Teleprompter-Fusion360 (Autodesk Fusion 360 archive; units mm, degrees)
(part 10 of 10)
sketch "Skizze119" plane through (0, 0, 4) normal (0, 0, 1) x axis (-1, 0, 0)
  line L1 (2.9968, -220.3404) -> (2.9969, -220.3404)
  line L2 (-0.0031, -167.3404) -> (-0.0031, -217.3404)
  line L3 (2.9969, -164.3404) -> (2.9968, -164.3404)
  line L4 (2.9969, -150.3404) -> (2.9969, -164.3404)
  line L5 (-362.0031, -150.3404) -> (2.9969, -150.3404)
  line L6 (-362.0031, -164.3404) -> (-362.0031, -150.3404)
  line L7 (-361.0031, -164.3404) -> (-362.0031, -164.3404)
  line L8 (-358.0031, -217.3404) -> (-358.0031, -167.3404)
  line L9 (-362.0031, -220.3404) -> (-361.0031, -220.3404)
  line L10 (-362.0031, -226.3404) -> (-362.0031, -220.3404)
  line L11 (-327.2391, -226.3404) -> (-362.0031, -226.3404)
  line L12 (-301.0031, -227.3404) -> (-325.0031, -227.3404)
  line L13 (-60.2391, -226.3404) -> (-298.767, -226.3404)
  line L14 (-34.0031, -227.3404) -> (-58.0031, -227.3404)
  line L15 (2.9969, -226.3404) -> (-31.767, -226.3404)
  line L16 (2.9969, -220.3404) -> (2.9969, -226.3404)
  line L17 (-199.3775, -150.3404) -> (-199.3775, -221.5209)
  line L18 (-159.3775, -150.3404) -> (-159.3775, -215.8403)
  circle C1 centre (-179.3775, -190) radius 20
  arc A1 centre (2.9969, -217.3404) radius 3 clockwise from (2.9968, -220.3404) to (-0.0031, -217.3404)
  arc A2 centre (2.9969, -167.3404) radius 3 clockwise from (-0.0031, -167.3404) to (2.9968, -164.3404)
  arc A3 centre (-361.0031, -167.3404) radius 3 clockwise from (-361.0031, -164.3404) to (-358.0031, -167.3404)
  arc A4 centre (-361.0031, -217.3404) radius 3 clockwise from (-358.0031, -217.3404) to (-361.0031, -220.3404)
  arc A5 centre (-325.0031, -224.3404) radius 3 clockwise from (-325.0031, -227.3404) to (-327.2391, -226.3404)
  arc A6 centre (-301.0031, -224.3404) radius 3 clockwise from (-298.767, -226.3404) to (-301.0031, -227.3404)
  arc A7 centre (-58.0031, -224.3404) radius 3 clockwise from (-58.0031, -227.3404) to (-60.2391, -226.3404)
  arc A8 centre (-34.0031, -224.3404) radius 3 clockwise from (-31.767, -226.3404) to (-34.0031, -227.3404)
  circle C2 centre (-179.3775, -170.3404) radius 20
  point P37 (-159.3775, -150.3404)
  point P38 (-199.3775, -150.3404)
  vertical L17
  perpendicular L13 L18
  tangent C1 L18
  tangent C1 L17
  coincident L5 P37
  coincident L5 P38
  tangent L18 C2
  tangent L5 C2
  tangent L17 C2
  dimension "d717" distance L17 L18 = 40
extrude "Extrusion122" cut sketch "Skizze119" profile of C1 L17 L18 C2 against normal blind 11
sketch "Skizze120" plane through (0, 0, -7) normal (0, 0, 1) x axis (-1, 0, 0)
  line L1 (-159.3775, -170.3404) -> (-159.3775, -190)
  line L2 (-199.3775, -190) -> (-199.3775, -170.3404)
  circle C1 centre (-179.3775, -190) radius 5.05
  arc A1 centre (-179.3775, -190) radius 20 clockwise from (-159.3775, -190) to (-199.3775, -190)
  arc A2 centre (-179.3775, -170.3404) radius 20 clockwise from (-199.3775, -170.3404) to (-159.3775, -170.3404)
  circle C2 centre (-179.3775, -170.3404) radius 5.05
  concentric A2 C2
  dimension "d720" diameter C2 = 10.1
extrude "Extrusion123" cut sketch "Skizze120" profile of C2 against normal blind 17
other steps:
base_feature "Basiselement1" bodies "vertical-brace"
base_feature "Basiselement2" bodies "Top Brace of Brio Holder"
named bodies: "Base", "Glas", "Side Left", "vertical-brace-orig", "Side Right", "vertical-brace", "Top Brace of DSLR Holder", "Back Brace of Camera Holder", "CameraPlate", "3DP-Glas-Abdeckung Right", "3DP-Glas-Abdeckung Left", "Stiffening Base Adapter", "Top Brace of Brio Holder", "gummi-nupsi1", "gummi-nupsi2"

design "Desklab-Screen"
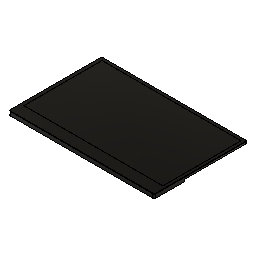
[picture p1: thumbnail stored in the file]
sketch "Skizze1" plane through (0, 0, 0) normal (0, 0, 1) x axis (1, 0, 0)
  line L1 (355.5, 0) -> (3.5, 0)
  line L2 (359, 225.5) -> (359, 3.5)
  line L3 (3.5, 229) -> (355.5, 229)
  line L4 (0, 3.5) -> (0, 225.5)
  arc A1 centre (3.5, 225.5) radius 3.5 clockwise from (0, 225.5) to (3.5, 229)
  arc A2 centre (355.5, 225.5) radius 3.5 clockwise from (355.5, 229) to (359, 225.5)
  arc A3 centre (355.5, 3.5) radius 3.5 clockwise from (359, 3.5) to (355.5, 0)
  arc A4 centre (3.5, 3.5) radius 3.5 clockwise from (3.5, 0) to (0, 3.5)
  point P1 (0, 0)
  point P2 (0, 0)
  point P4 (0, 229)
  point P3 (359, 0)
  horizontal L1
  vertical L2
  horizontal L3
  vertical L4
  coincident P1 P2
  coincident P4 L4
  coincident P4 L3
  tangent L4 A1
  tangent L3 A1
  tangent L3 A2
  tangent L2 A2
  coincident P3 L2
  coincident P3 L1
  tangent L2 A3
  tangent L1 A3
  coincident P2 L1
  coincident P2 L4
  tangent L1 A4
  tangent L4 A4
  dimension "d1" distance P2 P3 = 359
  dimension "d2" distance P2 P4 = 229
  dimension "d3" radius A1 = 3.5
  dimension "d4" radius A2 = 3.5
  dimension "d5" radius A3 = 3.5
  dimension "d6" radius A4 = 3.5
extrude "Extrusion1" new body sketch "Skizze1" along normal blind 6
sketch "Skizze2" plane through (0, 0, 0) normal (0, 0, -1) x axis (1, 0, 0)
  line L1 (0, -225.5) -> (0, -3.5)
  line L2 (355.5, -229) -> (3.5, -229)
  line L3 (359, -3.5) -> (359, -225.5)
  line L4 (3.5, 0) -> (355.5, 0)
  line L5 (359, -75) -> (0, -75)
  arc A1 centre (3.5, -3.5) radius 3.5 clockwise from (0, -3.5) to (3.5, 0)
  arc A2 centre (3.5, -225.5) radius 3.5 clockwise from (3.5, -229) to (0, -225.5)
  arc A3 centre (355.5, -225.5) radius 3.5 clockwise from (359, -225.5) to (355.5, -229)
  arc A4 centre (355.5, -3.5) radius 3.5 clockwise from (355.5, 0) to (359, -3.5)
  point P14 (0, -75)
  point P15 (359, -75)
  horizontal L5
  coincident L1 P14
  coincident L3 P15
  dimension "d9" distance L4 L5 = 75
extrude "Extrusion2" add sketch "Skizze2" profile of A1 L1 L3 A4 L4 L5 along normal blind 5
chamfer "Fase" distance 0.8
sketch "Skizze3" plane through (0, 0, 6) normal (0, 0, 1) x axis (-1, 0, 0)
  line L1 (-0.8, -3.5) -> (-0.8, -225.5)
  line L2 (-355.5, -0.8) -> (-3.5, -0.8)
  line L3 (-358.2, -225.5) -> (-358.2, -3.5)
  line L4 (-3.5, -228.2) -> (-355.5, -228.2)
  line L5 (-351.2, -28.8) -> (-8.8, -28.8)
  line L6 (-351.2, -221.2) -> (-351.2, -28.8)
  line L7 (-8.8, -221.2) -> (-351.2, -221.2)
  line L8 (-8.8, -28.8) -> (-8.8, -221.2)
  arc A1 centre (-3.5, -3.5) radius 2.7 clockwise from (-3.5, -0.8) to (-0.8, -3.5)
  arc A2 centre (-355.5, -3.5) radius 2.7 clockwise from (-358.2, -3.5) to (-355.5, -0.8)
  arc A3 centre (-355.5, -225.5) radius 2.7 clockwise from (-355.5, -228.2) to (-358.2, -225.5)
  arc A4 centre (-3.5, -225.5) radius 2.7 clockwise from (-0.8, -225.5) to (-3.5, -228.2)
  horizontal L5
  vertical L6
  horizontal L7
  vertical L8
  dimension "d13" distance L2 L5 = 28
  dimension "d14" distance L1 L8 = 8
  dimension "d15" distance L3 L6 = 7
  dimension "d16" distance L4 L7 = 7
extrude "Extrusion3" cut sketch "Skizze3" profile of L5 L6 L7 L8 against normal blind 0.5

design "TV-Adapter"
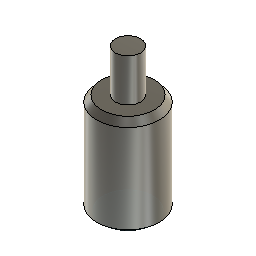
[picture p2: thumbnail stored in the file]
sketch "Skizze1" plane through (0, 0, 0) normal (0, 0, 1) x axis (1, 0, 0)
  circle C1 centre (0, 0) radius 12.5
  point P1 (0, 0)
  point P2 (0, 0)
  coincident P1 P2
  dimension "d1" diameter C1 = 25
extrude "Extrusion1" new body sketch "Skizze1" along normal blind 40
chamfer "Fase" distance 2 distance 2.5
sketch "Skizze2" plane through (0, 0, 40) normal (0, 0, 1) x axis (-1, 0, 0)
  circle C1 centre (0, 0) radius 10.5
  circle C2 centre (0, 0) radius 5
  point P1 (0, 0)
  point P3 (0, 0)
  coincident P1 P3
  dimension "d6" diameter C2 = 10
extrude "Extrusion2" add sketch "Skizze2" profile of C2 along normal blind 17
sketch "Skizze3" plane through (0, 0, 0) normal (0, 0, -1) x axis (1, 0, 0)
  circle C1 centre (0, 0) radius 10
component_from_bodies "Körper->Berechn"
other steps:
base_feature "Basiselement"
create_component "Komponente erstellen"
remove_body "Körper entfernen"

design "Logitech-Brio"
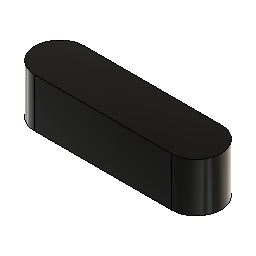
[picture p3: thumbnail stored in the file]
sketch "Skizze" plane through (0, 0, 0) normal (0, 0, 1) x axis (1, 0, 0)
  line L1 (89.25, 0) -> (13.75, 0)
  line L2 (13.75, 27.5) -> (89.25, 27.5)
  arc A1 centre (13.75, 13.75) radius 13.75 clockwise from (0, 13.75) to (13.75, 27.5)
  arc A2 centre (13.75, 13.75) radius 13.75 clockwise from (13.75, 0) to (13.75, 27.5)
  arc A3 centre (89.25, 13.75) radius 13.75 clockwise from (89.25, 27.5) to (103, 13.75)
  arc A4 centre (89.25, 13.75) radius 13.75 clockwise from (89.25, 27.5) to (89.25, 0)
  point P2 (0, 27.5)
  point P1 (0, 0)
  horizontal L1
  horizontal L2
  coincident P2 L2
  tangent L2 A1
  concentric A1 A2
  tangent L2 A3
  concentric A3 A4
  dimension "d2" distance P1 P2 = 27.5
  dimension "d3" radius A1 = 13.75 (= "( 27.5 / 2 ) * 1 mm")
  dimension "d4" radius A3 = 13.75
extrude "Extrusion" new body sketch "Skizze" along normal blind 27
